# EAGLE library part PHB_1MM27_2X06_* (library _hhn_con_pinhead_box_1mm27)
Pin Header Box-Type, 1.27mm/0.5"/50mil Pitch, 2x06 Circuits Note: see library description for an important note about THT-version
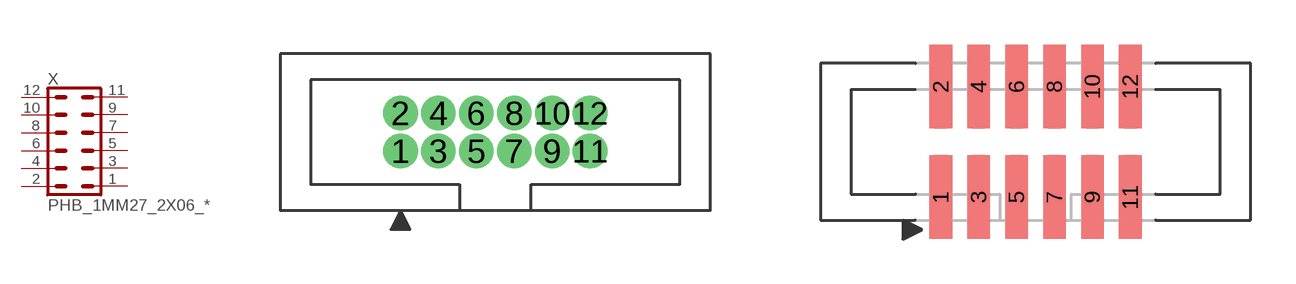
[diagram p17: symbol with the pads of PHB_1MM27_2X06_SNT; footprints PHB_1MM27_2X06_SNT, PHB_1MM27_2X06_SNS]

Designator prefix X

## PHB_1MM27_2X06_SNT  [PHB_1MM27_2X06_SNT]
1  1  pas
2  2  pas
3  3  pas
4  4  pas
5  5  pas
6  6  pas
7  7  pas
8  8  pas
9  9  pas
10  10  pas
11  11  pas
12  12  pas

## PHB_1MM27_2X06_SNS  [PHB_1MM27_2X06_SNS]
Pads as for PHB_1MM27_2X06_SNT

## Footprint PHB_1MM27_2X06_SNT (pad centres in mm)
Pin Header Box-Type, 1.27mm Pitch, 2x06 circuits, Straight, No Locking, THT Important Note: Diameter in this lbr is set to a specific value (NOT 'auto' = 0), this is ignored by actual eagle versions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
drill 0.65 pad 1 round: 1 -3.175,-0.635; 2 -3.175,0.635; 3 -1.905,-0.635; 4 -1.905,0.635; 5 -0.635,-0.635; 6 -0.635,0.635; 7 0.635,-0.635; 8 0.635,0.635; 9 1.905,-0.635; 10 1.905,0.635; 11 3.175,-0.635; 12 3.175,0.635

## Footprint PHB_1MM27_2X06_SNS (pad centres in mm)
Pin Header Box-Type, 1.27mm Pitch, 2x06 circuits, Straight, No Locking, SMT
smd 0.76 x 2.8: 1 -3.175,-1.85; 2 -3.175,1.85; 3 -1.905,-1.85; 4 -1.905,1.85; 5 -0.635,-1.85; 6 -0.635,1.85; 7 0.635,-1.85; 8 0.635,1.85; 9 1.905,-1.85; 10 1.905,1.85; 11 3.175,-1.85; 12 3.175,1.85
